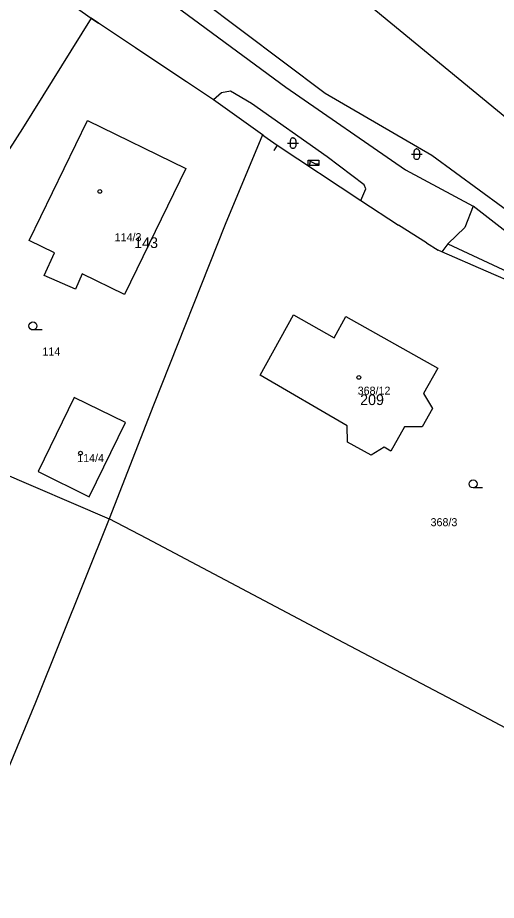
# Model space of a CAD drawing. Extents: x -836739 to -835945, y -1070775 to -1070126.
# Drawn here: x -836458 to -836413.1, y -1070448 to -1070365.3 of the extents above; entities that cross this region are included whole.
import ezdxf

# ---------------------------------------------------------------- set-up
doc = ezdxf.new("R2010")
doc.units = 0
for name, color, linetype in [('BodPole_mer', 7, 'Continuous'), ('Budovy_hranice', 7, 'Continuous'), ('Budovy_kody', 7, 'Continuous'), ('Doprava_hranice', 7, 'Continuous'), ('OstPloch_hranice', 7, 'Continuous'), ('OstPloch_kody', 7, 'Continuous'), ('PovrZnIS_body', 7, 'Continuous'), ('PovrZnIS_hranice', 7, 'Continuous'), ('RuianAdr_popis', 7, 'Continuous'), ('RuianPar_popis', 7, 'Continuous'), ('Stavby_linie', 7, 'Continuous')]:
    doc.layers.add(name, color=color, linetype=linetype)

msp = doc.modelspace()

# ---------------------------------------------------------------- linework, layer by layer
at = {"layer": 'BodPole_mer'}
for p, q in [((-836451.09, -1070365.35), (-836451.09, -1070365.35)), ((-836450.4, -1070365.82), (-836450.4, -1070365.82)), ((-836450.4, -1070365.82), (-836450.4, -1070365.82)), ((-836446.93, -1070368.12), (-836446.93, -1070368.12)), ((-836446.93, -1070368.12), (-836446.93, -1070368.12)), ((-836444.56, -1070369.72), (-836444.56, -1070369.72)), ((-836444.56, -1070369.72), (-836444.56, -1070369.72)), ((-836442.16, -1070371.3), (-836442.16, -1070371.3)), ((-836442.16, -1070371.3), (-836442.16, -1070371.3)), ((-836438.05, -1070372.2), (-836438.05, -1070372.2)), ((-836432.86, -1070371.82), (-836432.86, -1070371.82)), ((-836439.62, -1070372.99), (-836439.62, -1070372.99)), ((-836439.62, -1070372.99), (-836439.62, -1070372.99)), ((-836438.88, -1070372.34), (-836438.88, -1070372.34)), ((-836429.17, -1070372.36), (-836429.17, -1070372.36)), ((-836436.06, -1070373.33), (-836436.06, -1070373.33)), ((-836451.44, -1070374.93), (-836451.44, -1070374.93)), ((-836457.52, -1070375.69), (-836457.52, -1070375.69)), ((-836435.05, -1070376.27), (-836435.05, -1070376.27)), ((-836434.9, -1070376.37), (-836434.9, -1070376.37)), ((-836433.98, -1070377.74), (-836433.98, -1070377.74)), ((-836433.65, -1070377.25), (-836433.65, -1070377.25)), ((-836428.99, -1070378.33), (-836428.99, -1070378.33)), ((-836419.16, -1070378.17), (-836419.16, -1070378.17)), ((-836442.21, -1070379.44), (-836442.21, -1070379.44)), ((-836430.26, -1070378.9), (-836430.26, -1070378.9)), ((-836430.26, -1070378.9), (-836430.26, -1070378.9)), ((-836421.65, -1070379.55), (-836421.65, -1070379.55)), ((-836425.52, -1070380.96), (-836425.52, -1070380.96)), ((-836425.36, -1070381.34), (-836425.36, -1070381.34)), ((-836425.81, -1070382.43), (-836425.81, -1070382.43)), ((-836415.3, -1070382.95), (-836415.3, -1070382.95)), ((-836438.54, -1070384.68), (-836438.54, -1070384.68)), ((-836422.29, -1070384.74), (-836422.29, -1070384.74)), ((-836416.08, -1070384.95), (-836416.08, -1070384.95)), ((-836456.9, -1070386.18), (-836456.9, -1070386.18)), ((-836419.68, -1070386.4), (-836419.68, -1070386.4)), ((-836419.68, -1070386.4), (-836419.68, -1070386.4)), ((-836418.59, -1070387.07), (-836418.59, -1070387.07)), ((-836417.67, -1070386.5), (-836417.67, -1070386.5)), ((-836454.54, -1070387.32), (-836454.54, -1070387.32)), ((-836418.22, -1070387.23), (-836418.22, -1070387.23)), ((-836455.49, -1070389.47), (-836455.49, -1070389.47)), ((-836451.92, -1070389.29), (-836451.92, -1070389.29)), ((-836414.08, -1070389.04), (-836414.08, -1070389.04)), ((-836452.57, -1070390.74), (-836452.57, -1070390.74)), ((-836447.98, -1070391.25), (-836447.98, -1070391.25)), ((-836432.13, -1070393.14), (-836432.13, -1070393.14)), ((-836427.22, -1070393.31), (-836427.22, -1070393.31)), ((-836428.33, -1070395.3), (-836428.33, -1070395.3)), ((-836418.61, -1070398.15), (-836418.61, -1070398.15)), ((-836435.26, -1070398.78), (-836435.26, -1070398.78)), ((-836452.68, -1070400.88), (-836452.68, -1070400.88)), ((-836419.94, -1070400.5), (-836419.94, -1070400.5)), ((-836445.25, -1070401.61), (-836445.25, -1070401.61)), ((-836419.12, -1070401.9), (-836419.12, -1070401.9)), ((-836447.89, -1070403.24), (-836447.89, -1070403.24)), ((-836427.09, -1070403.54), (-836427.09, -1070403.54)), ((-836421.72, -1070403.64), (-836421.72, -1070403.64)), ((-836420.07, -1070403.62), (-836420.07, -1070403.62)), ((-836427.06, -1070405.06), (-836427.06, -1070405.06)), ((-836423.64, -1070405.55), (-836423.64, -1070405.55)), ((-836423.01, -1070405.92), (-836423.01, -1070405.92)), ((-836424.86, -1070406.28), (-836424.86, -1070406.28)), ((-836456.06, -1070407.83), (-836456.06, -1070407.83)), ((-836451.29, -1070410.18), (-836451.29, -1070410.18)), ((-836449.39, -1070412.25), (-836449.39, -1070412.25)), ((-836445.87, -1070414.08), (-836445.87, -1070414.08)), ((-836428, -1070423.55), (-836428, -1070423.55)), ((-836456.32, -1070429.46), (-836456.32, -1070429.46)), ((-836415.3, -1070430.25), (-836415.3, -1070430.25))]:
    msp.add_line(p, q, dxfattribs=at)
at = {"layer": 'Budovy_hranice'}
for p, q in [((-836451.44, -1070374.93), (-836442.21, -1070379.44)), ((-836442.21, -1070379.44), (-836447.98, -1070391.25))]:
    msp.add_line(p, q, dxfattribs=at)
for points in [[(-836447.98, -1070391.25), (-836451.92, -1070389.29), (-836452.57, -1070390.74), (-836455.49, -1070389.47), (-836454.54, -1070387.32), (-836456.9, -1070386.18), (-836451.44, -1070374.93)], [(-836427.22, -1070393.31), (-836418.61, -1070398.15), (-836419.94, -1070400.5), (-836419.12, -1070401.9), (-836420.07, -1070403.62), (-836421.72, -1070403.64), (-836423.01, -1070405.92), (-836423.64, -1070405.55), (-836424.86, -1070406.28), (-836427.06, -1070405.06), (-836427.09, -1070403.54), (-836435.26, -1070398.78), (-836432.13, -1070393.14), (-836428.33, -1070395.3), (-836427.22, -1070393.31)], [(-836456.06, -1070407.83), (-836451.29, -1070410.18), (-836447.89, -1070403.24), (-836452.68, -1070400.88), (-836456.06, -1070407.83)]]:
    msp.add_lwpolyline(points, dxfattribs=at)
at = {"layer": 'Budovy_kody'}
for centre in [(-836450.28, -1070381.58), (-836426.01, -1070399), (-836452.09, -1070406.1)]:
    msp.add_circle(centre, 0.175, dxfattribs=at)
at = {"layer": 'Doprava_hranice'}
for points in [[(-836496.52, -1070319.54), (-836488.05, -1070326.94), (-836479.74, -1070333.71), (-836473.51, -1070339.57), (-836464.27, -1070347.56), (-836456.25, -1070354.2), (-836445.54, -1070362.45), (-836432.86, -1070371.82), (-836421.65, -1070379.55), (-836415.3, -1070382.95)], [(-836490.91, -1070321.78), (-836479.74, -1070331.15), (-836472.55, -1070338.03), (-836463.6, -1070345.51), (-836457.27, -1070350.28), (-836449.01, -1070356.39), (-836440.87, -1070363.54), (-836429.17, -1070372.36), (-836419.16, -1070378.17), (-836410.31, -1070384.67), (-836403.72, -1070387.61), (-836401.28, -1070388.23), (-836398.49, -1070390.5), (-836396.2, -1070392.51)], [(-836425.81, -1070382.43), (-836425.36, -1070381.34), (-836425.52, -1070380.96), (-836428.99, -1070378.33), (-836436.06, -1070373.33), (-836438.05, -1070372.2), (-836438.88, -1070372.34), (-836439.62, -1070372.99)], [(-836415.3, -1070382.95), (-836416.08, -1070384.95), (-836417.67, -1070386.5), (-836418.22, -1070387.23)], [(-836363.94, -1070405.58), (-836375.83, -1070400.5), (-836396.2, -1070392.51), (-836412.22, -1070385.35), (-836415.3, -1070382.95)], [(-836417.67, -1070386.5), (-836404.61, -1070392.58), (-836394.98, -1070396.26), (-836377.21, -1070403.49), (-836366.86, -1070407.51), (-836361.89, -1070409.63)]]:
    msp.add_lwpolyline(points, dxfattribs=at)
at = {"layer": 'OstPloch_hranice'}
msp.add_lwpolyline([(-836356.62, -1070406.87), (-836370.19, -1070399.44), (-836385.43, -1070392.2), (-836396.38, -1070386.03), (-836404.41, -1070381.11), (-836409.87, -1070376.61), (-836425.28, -1070363.93), (-836449.03, -1070345.44), (-836455, -1070340), (-836462.64, -1070329.11), (-836464.81, -1070325.47), (-836465.74, -1070321.03), (-836464.89, -1070314.87), (-836461.62, -1070306.74), (-836456.41, -1070297.54), (-836450.95, -1070288.2), (-836447.03, -1070272.79), (-836441.38, -1070260.76)], dxfattribs=at)
at = {"layer": 'OstPloch_kody'}
for p, q in [((-836432.68, -1070377.06), (-836431.68, -1070377.06)), ((-836432.43, -1070377.31), (-836432.43, -1070376.81)), ((-836431.93, -1070376.81), (-836431.93, -1070377.31)), ((-836420.84, -1070378.35), (-836420.84, -1070377.85)), ((-836420.34, -1070377.85), (-836420.34, -1070378.35)), ((-836421.09, -1070378.1), (-836420.09, -1070378.1)), ((-836455.675, -1070394.56), (-836456.55, -1070394.56)), ((-836414.425, -1070409.36), (-836415.3, -1070409.36))]:
    msp.add_line(p, q, dxfattribs=at)
for points in [[(-836432.18, -1070376.56), (-836432.225, -1070376.564), (-836432.272, -1070376.578), (-836432.317, -1070376.601), (-836432.357, -1070376.633), (-836432.389, -1070376.673), (-836432.412, -1070376.718), (-836432.426, -1070376.765), (-836432.43, -1070376.81)], [(-836432.18, -1070376.56), (-836432.135, -1070376.564), (-836432.088, -1070376.578), (-836432.043, -1070376.601), (-836432.003, -1070376.633), (-836431.971, -1070376.673), (-836431.948, -1070376.718), (-836431.934, -1070376.765), (-836431.93, -1070376.81)], [(-836432.18, -1070377.56), (-836432.225, -1070377.556), (-836432.272, -1070377.542), (-836432.317, -1070377.519), (-836432.357, -1070377.487), (-836432.389, -1070377.447), (-836432.412, -1070377.402), (-836432.426, -1070377.355), (-836432.43, -1070377.31)], [(-836431.93, -1070377.31), (-836431.934, -1070377.355), (-836431.948, -1070377.402), (-836431.971, -1070377.447), (-836432.003, -1070377.487), (-836432.043, -1070377.519), (-836432.088, -1070377.542), (-836432.135, -1070377.556), (-836432.18, -1070377.56)], [(-836420.59, -1070377.6), (-836420.635, -1070377.604), (-836420.682, -1070377.618), (-836420.727, -1070377.641), (-836420.767, -1070377.673), (-836420.799, -1070377.713), (-836420.822, -1070377.758), (-836420.836, -1070377.805), (-836420.84, -1070377.85)], [(-836420.59, -1070377.6), (-836420.545, -1070377.604), (-836420.498, -1070377.618), (-836420.453, -1070377.641), (-836420.413, -1070377.673), (-836420.381, -1070377.713), (-836420.358, -1070377.758), (-836420.344, -1070377.805), (-836420.34, -1070377.85)], [(-836420.59, -1070378.6), (-836420.635, -1070378.596), (-836420.682, -1070378.582), (-836420.727, -1070378.559), (-836420.767, -1070378.527), (-836420.799, -1070378.487), (-836420.822, -1070378.442), (-836420.836, -1070378.395), (-836420.84, -1070378.35)], [(-836420.34, -1070378.35), (-836420.344, -1070378.395), (-836420.358, -1070378.442), (-836420.381, -1070378.487), (-836420.413, -1070378.527), (-836420.453, -1070378.559), (-836420.498, -1070378.582), (-836420.545, -1070378.596), (-836420.59, -1070378.6)]]:
    msp.add_lwpolyline(points, dxfattribs=at)
for centre in [(-836456.55, -1070394.185), (-836415.3, -1070408.985)]:
    msp.add_ellipse(centre, major_axis=(0.375, 0), ratio=0.999999, dxfattribs=at)
at = {"layer": 'PovrZnIS_body'}
for p, q in [((-836430.76, -1070378.651), (-836429.76, -1070378.649)), ((-836430.76, -1070378.651), (-836429.76, -1070378.649)), ((-836430.76, -1070379.151), (-836430.76, -1070378.651)), ((-836430.76, -1070379.151), (-836430.76, -1070378.651)), ((-836430.571, -1070378.985), (-836430.571, -1070378.735)), ((-836430.571, -1070378.735), (-836430.071, -1070378.984)), ((-836430.571, -1070378.985), (-836430.571, -1070378.735)), ((-836430.571, -1070378.735), (-836430.071, -1070378.984)), ((-836429.76, -1070378.649), (-836429.76, -1070379.149)), ((-836429.76, -1070378.649), (-836429.76, -1070379.149)), ((-836429.76, -1070379.149), (-836430.76, -1070379.151)), ((-836429.76, -1070379.149), (-836430.76, -1070379.151)), ((-836430.681, -1070378.985), (-836430.571, -1070378.985)), ((-836430.681, -1070378.985), (-836430.571, -1070378.985)), ((-836430.071, -1070378.984), (-836429.826, -1070378.983)), ((-836430.071, -1070378.984), (-836429.826, -1070378.983))]:
    msp.add_line(p, q, dxfattribs=at)
at = {"layer": 'PovrZnIS_hranice'}
for p, q in [((-836451.09, -1070365.35), (-836450.4, -1070365.82)), ((-836451.09, -1070365.35), (-836450.4, -1070365.82)), ((-836434.9, -1070376.37), (-836433.65, -1070377.25)), ((-836433.65, -1070377.25), (-836433.98, -1070377.74))]:
    msp.add_line(p, q, dxfattribs=at)
at = {"layer": 'RuianAdr_popis'}
for p, q in [((-836447.06, -1070386.88), (-836447.06, -1070386.88)), ((-836425.89, -1070401.59), (-836425.89, -1070401.59))]:
    msp.add_line(p, q, dxfattribs=at)
at = {"layer": 'RuianPar_popis'}
for p, q in [((-836448.89, -1070386.24), (-836448.89, -1070386.24)), ((-836455.66, -1070396.95), (-836455.66, -1070396.95)), ((-836426.12, -1070400.62), (-836426.12, -1070400.62)), ((-836452.4, -1070406.93), (-836452.4, -1070406.93)), ((-836419.29, -1070412.94), (-836419.29, -1070412.94))]:
    msp.add_line(p, q, dxfattribs=at)
at = {"layer": 'Stavby_linie'}
for p, q in [((-836452.99, -1070364.02), (-836451.09, -1070365.35)), ((-836450.4, -1070365.82), (-836451.09, -1070365.35)), ((-836450.4, -1070365.82), (-836451.09, -1070365.35)), ((-836446.93, -1070368.12), (-836450.4, -1070365.82)), ((-836446.93, -1070368.12), (-836450.4, -1070365.82)), ((-836444.56, -1070369.72), (-836446.93, -1070368.12)), ((-836444.56, -1070369.72), (-836446.93, -1070368.12)), ((-836442.16, -1070371.3), (-836444.56, -1070369.72)), ((-836442.16, -1070371.3), (-836444.56, -1070369.72)), ((-836439.62, -1070372.99), (-836442.16, -1070371.3)), ((-836439.62, -1070372.99), (-836442.16, -1070371.3)), ((-836435.05, -1070376.27), (-836439.62, -1070372.99)), ((-836435.05, -1070376.27), (-836439.62, -1070372.99)), ((-836434.9, -1070376.37), (-836435.05, -1070376.27)), ((-836434.9, -1070376.37), (-836435.05, -1070376.27)), ((-836425.81, -1070382.43), (-836422.29, -1070384.74)), ((-836419.68, -1070386.4), (-836422.29, -1070384.74)), ((-836419.68, -1070386.4), (-836422.29, -1070384.74)), ((-836419.68, -1070386.4), (-836418.59, -1070387.07)), ((-836419.68, -1070386.4), (-836418.59, -1070387.07)), ((-836470.4, -1070403.24), (-836449.39, -1070412.25))]:
    msp.add_line(p, q, dxfattribs=at)
for points in [[(-836451.09, -1070365.35), (-836457.52, -1070375.69), (-836459.45, -1070378.71), (-836464.64, -1070390.16), (-836469.09, -1070399.98), (-836470.4, -1070403.24)], [(-836435.05, -1070376.27), (-836438.54, -1070384.68), (-836445.25, -1070401.61), (-836449.39, -1070412.25)], [(-836434.9, -1070376.37), (-836433.65, -1070377.25), (-836425.81, -1070382.43)], [(-836393.4, -1070397.9), (-836405, -1070392.97), (-836414.08, -1070389.04), (-836418.22, -1070387.23), (-836418.59, -1070387.07)], [(-836449.39, -1070412.25), (-836456.32, -1070429.46), (-836463.2, -1070446.07), (-836469.22, -1070461.85), (-836476.75, -1070482.14), (-836479.99, -1070490.54)], [(-836407.72, -1070434.26), (-836415.3, -1070430.25), (-836428, -1070423.55), (-836445.87, -1070414.08), (-836449.39, -1070412.25)]]:
    msp.add_lwpolyline(points, dxfattribs=at)

# ---------------------------------------------------------------- texts
at = {"layer": 'RuianAdr_popis'}
for s, p in [('143', (-836447.06, -1070386.88)), ('209', (-836425.89, -1070401.59))]:
    msp.add_text(s, height=1, dxfattribs=at).set_placement(p)
at = {"layer": 'RuianPar_popis'}
for s, p in [('114/3', (-836448.89, -1070386.24)), ('114', (-836455.66, -1070396.95)), ('368/12', (-836426.12, -1070400.62)), ('114/4', (-836452.4, -1070406.93)), ('368/3', (-836419.29, -1070412.94))]:
    msp.add_text(s, height=0.75, dxfattribs=at).set_placement(p)

doc.saveas('drawing.dxf')
